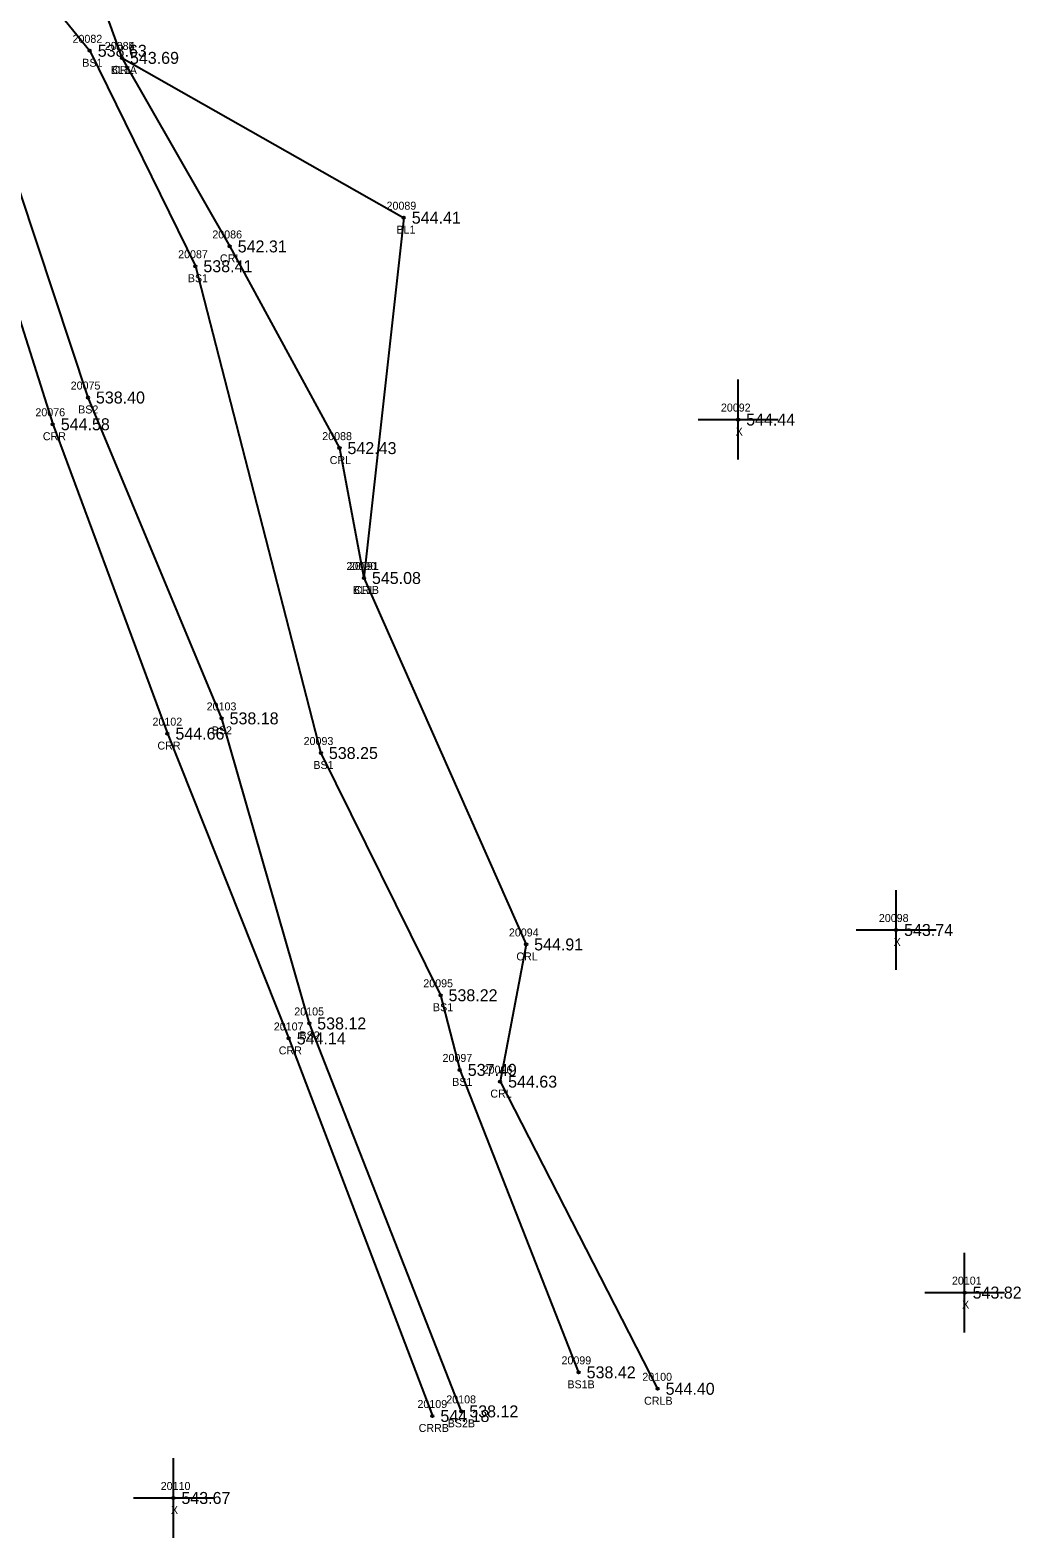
# Model space of a CAD drawing. Extents: x 1540443 to 1541844, y 887157 to 888162.
# Drawn here: x 1541285 to 1541409.1, y 887157 to 887345.9 of the extents above; entities that cross this region are included whole.
import ezdxf

# ---------------------------------------------------------------- set-up
doc = ezdxf.new("R2010")
doc.units = 0
for name, color, linetype in [('RD_DTM_BkLn1', 7, 'Continuous'), ('RD_DTM_BkLn2', 7, 'Continuous'), ('RD_DTM_BkLn_txCode', 7, 'Continuous'), ('RD_EX_H2O', 7, 'Continuous'), ('RD_EX_H2O_txCode', 7, 'Continuous'), ('RD_EX_Misc', 7, 'Continuous'), ('RD_EX_Misc_txCode', 7, 'Continuous'), ('RD_EX_TX_H2O_ELEV', 7, 'Continuous'), ('RD_EX_TX_Misc_ELEV', 7, 'Continuous'), ('RD_SMD_Locator', 7, 'Continuous')]:
    doc.layers.add(name, color=color, linetype=linetype)

msp = doc.modelspace()

# ---------------------------------------------------------------- linework, layer by layer
at = {"layer": 'RD_DTM_BkLn1'}
msp.add_lwpolyline([(1541296.54, 887342.39), (1541331.82, 887322.37), (1541326.83, 887277.23)], dxfattribs=at)
at = {"layer": 'RD_DTM_BkLn2'}
for points in [[(1541154.57, 887667.56), (1541160.17, 887655.15), (1541167.27, 887653.55), (1541180.97, 887604.84), (1541187.58, 887570.43), (1541210.64, 887527.72), (1541238.36, 887493.82), (1541248.3, 887440.2), (1541253.39, 887402.02), (1541268.17, 887373.2), (1541292.51, 887343.28), (1541305.73, 887316.29), (1541321.44, 887255.3), (1541336.42, 887224.95), (1541338.83, 887215.6), (1541353.71, 887177.71)], [(1541146.1, 887665.49), (1541150.74, 887637.01), (1541158.36, 887596.65), (1541173.42, 887559.93), (1541207.19, 887515.92), (1541227.14, 887479.24), (1541238.45, 887421.16), (1541256.87, 887373.46), (1541277.28, 887344.99), (1541292.28, 887299.84), (1541309.01, 887259.64), (1541319.98, 887221.42), (1541339.02, 887172.82)]]:
    msp.add_lwpolyline(points, dxfattribs=at)
at = {"layer": 'RD_EX_H2O'}
for points in [[(1541162.66, 887669.25), (1541171.26, 887657.22), (1541176.19, 887641.21), (1541191.34, 887607.73), (1541196.49, 887563.9), (1541212.86, 887537.67), (1541231.05, 887519.4), (1541238.36, 887501.63), (1541241.27, 887497.71), (1541242.57, 887490.48), (1541255.99, 887444.22), (1541265.96, 887413.11), (1541283.07, 887379.68), (1541296.54, 887342.39), (1541310.03, 887318.77), (1541323.77, 887293.5), (1541326.83, 887277.23), (1541347.14, 887231.32), (1541343.88, 887214.13), (1541363.6, 887175.65)], [(1541139.32, 887662.55), (1541137.72, 887649.7), (1541145.14, 887602.62), (1541162.15, 887562.57), (1541203.5, 887513.91), (1541216.11, 887476.29), (1541233.11, 887419.79), (1541253.41, 887371.38), (1541273.08, 887343.25), (1541287.88, 887296.49), (1541302.23, 887257.73), (1541317.42, 887219.54), (1541335.4, 887172.24)]]:
    msp.add_lwpolyline(points, dxfattribs=at)
at = {"layer": 'RD_EX_Misc'}
for p, q in [((1541373.68, 887292.08), (1541373.68, 887302.08)), ((1541368.68, 887297.08), (1541378.68, 887297.08)), ((1541393.45, 887228.13), (1541393.45, 887238.13)), ((1541388.45, 887233.13), (1541398.45, 887233.13)), ((1541402.03, 887182.7), (1541402.03, 887192.7)), ((1541397.03, 887187.7), (1541407.03, 887187.7)), ((1541302.98, 887156.97), (1541302.98, 887166.97)), ((1541297.98, 887161.97), (1541307.98, 887161.97))]:
    msp.add_line(p, q, dxfattribs=at)
at = {"layer": 'RD_SMD_Locator'}
for centre in [(1541292.51, 887343.28), (1541296.54, 887342.39), (1541296.54, 887342.39), (1541331.82, 887322.37), (1541310.03, 887318.77), (1541305.73, 887316.29), (1541292.28, 887299.84), (1541287.88, 887296.49), (1541373.68, 887297.08), (1541323.77, 887293.5), (1541326.83, 887277.23), (1541326.83, 887277.23), (1541309.01, 887259.64), (1541302.23, 887257.73), (1541321.44, 887255.3), (1541393.45, 887233.13), (1541347.14, 887231.32), (1541336.42, 887224.95), (1541319.98, 887221.42), (1541317.42, 887219.54), (1541338.83, 887215.6), (1541343.88, 887214.13), (1541402.03, 887187.7), (1541353.71, 887177.71), (1541363.6, 887175.65), (1541335.4, 887172.24), (1541339.02, 887172.82), (1541302.98, 887161.97)]:
    msp.add_circle(centre, 0.15, dxfattribs=at)

# ---------------------------------------------------------------- texts
at = {"layer": 'RD_DTM_BkLn_txCode'}
for s, p in [('20082', (1541290.35, 887344.28)), ('20085', (1541294.39, 887343.39)), ('BS1', (1541291.57, 887341.28)), ('BL1A', (1541295.13, 887340.39)), ('20089', (1541329.66, 887323.37)), ('BL1', (1541330.9, 887320.37)), ('20087', (1541303.57, 887317.29)), ('BS1', (1541304.78, 887314.29)), ('20075', (1541290.12, 887300.84)), ('BS2', (1541291.05, 887297.84)), ('20090', (1541324.64, 887278.23)), ('BL1B', (1541325.44, 887275.23)), ('20103', (1541307.14, 887260.64)), ('BS2', (1541307.78, 887257.64)), ('20093', (1541319.28, 887256.3)), ('BS1', (1541320.5, 887253.3)), ('20095', (1541334.26, 887225.95)), ('20105', (1541318.11, 887222.42)), ('BS1', (1541335.47, 887222.95)), ('BS2', (1541318.76, 887219.42)), ('20097', (1541336.67, 887216.6)), ('BS1', (1541337.88, 887213.6)), ('20099', (1541351.56, 887178.71)), ('BS1B', (1541352.3, 887175.71)), ('20108', (1541337.14, 887173.82)), ('BS2B', (1541337.32, 887170.82))]:
    msp.add_text(s, height=1, dxfattribs=at).set_placement(p)
at = {"layer": 'RD_EX_H2O_txCode'}
for s, p in [('20084', (1541294.39, 887343.39)), ('CRL', (1541295.31, 887340.39)), ('20086', (1541307.85, 887319.77)), ('CRL', (1541308.8, 887316.77)), ('20076', (1541285.7, 887297.49)), ('CRR', (1541286.63, 887294.49)), ('20088', (1541321.61, 887294.5)), ('CRL', (1541322.54, 887291.5)), ('20091', (1541324.96, 887278.23)), ('CRL', (1541325.61, 887275.23)), ('20102', (1541300.36, 887258.73)), ('CRR', (1541300.98, 887255.73)), ('20094', (1541344.98, 887232.32)), ('CRL', (1541345.91, 887229.32)), ('20107', (1541315.55, 887220.54)), ('CRR', (1541316.17, 887217.54)), ('20096', (1541341.7, 887215.13)), ('CRL', (1541342.65, 887212.13)), ('20100', (1541361.68, 887176.65)), ('20109', (1541333.53, 887173.24)), ('CRLB', (1541361.9, 887173.65)), ('CRRB', (1541333.68, 887170.24))]:
    msp.add_text(s, height=1, dxfattribs=at).set_placement(p)
at = {"layer": 'RD_EX_Misc_txCode'}
for s, p in [('20092', (1541371.52, 887298.08)), ('X', (1541373.36, 887295.08)), ('20098', (1541391.29, 887234.13)), ('X', (1541393.14, 887231.13)), ('20101', (1541400.44, 887188.7)), ('X', (1541401.71, 887185.7)), ('20110', (1541301.39, 887162.97)), ('X', (1541302.67, 887159.97))]:
    msp.add_text(s, height=1, dxfattribs=at).set_placement(p)
at = {"layer": 'RD_EX_TX_H2O_ELEV'}
for s, p in [('543.69', (1541297.54, 887341.64)), ('542.31', (1541311.03, 887318.02)), ('544.58', (1541288.88, 887295.74)), ('542.43', (1541324.77, 887292.75)), ('545.08', (1541327.83, 887276.48)), ('544.66', (1541303.23, 887256.98)), ('544.91', (1541348.14, 887230.57)), ('544.14', (1541318.42, 887218.79)), ('544.63', (1541344.88, 887213.38)), ('544.40', (1541364.6, 887174.9)), ('544.18', (1541336.4, 887171.49))]:
    msp.add_text(s, height=1.5, dxfattribs=at).set_placement(p)
at = {"layer": 'RD_EX_TX_Misc_ELEV'}
for s, p in [('538.63', (1541293.51, 887342.53)), ('543.69', (1541297.54, 887341.64)), ('544.41', (1541332.82, 887321.62)), ('538.41', (1541306.73, 887315.54)), ('538.40', (1541293.28, 887299.09)), ('544.44', (1541374.68, 887296.33)), ('545.08', (1541327.83, 887276.48)), ('538.18', (1541310.01, 887258.89)), ('538.25', (1541322.44, 887254.55)), ('543.74', (1541394.45, 887232.38)), ('538.22', (1541337.42, 887224.2)), ('538.12', (1541320.98, 887220.67)), ('537.49', (1541339.83, 887214.85)), ('543.82', (1541403.03, 887186.95)), ('538.42', (1541354.71, 887176.96)), ('538.12', (1541340.02, 887172.07)), ('543.67', (1541303.98, 887161.22))]:
    msp.add_text(s, height=1.5, dxfattribs=at).set_placement(p)

doc.saveas('drawing.dxf')
